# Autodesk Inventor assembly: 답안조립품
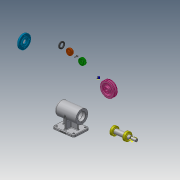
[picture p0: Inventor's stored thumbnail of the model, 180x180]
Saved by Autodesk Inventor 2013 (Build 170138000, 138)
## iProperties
Created: 2020-10
Part Number: 답안조립품
Document SubType Name: Assembly
Designer: 19
Author: 19
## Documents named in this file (12)
- C:\Users\user\Desktop\701004V1023\답안조립품.iam
- C:\Users\user\Desktop\701004V1023\본체.ipt
- C:\Users\user\Desktop\701004V1023\Ű 5 x 5 x 16.ipt
- C:\Users\user\Desktop\701004V1023\V벨트풀리.ipt
- C:\Users\user\Desktop\701004V1023\멈춤나사 M3.ipt
- C:\Users\user\Desktop\701004V1023\베어링 6004.ipt
- C:\Users\user\Desktop\701004V1023\베어링 51202.ipt
- C:\Users\user\Desktop\701004V1023\볼트 M4.ipt
- C:\Users\user\Desktop\701004V1023\어댑터슬리브.ipt
- C:\Users\user\Desktop\701004V1023\오일 실.ipt
- C:\Users\user\Desktop\701004V1023\축.ipt
- C:\Users\user\Desktop\701004V1023\커버.ipt
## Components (2 placed, 2 different names)
1. Ű 5 x 5 x 16:1
2. V벨트풀리:1
